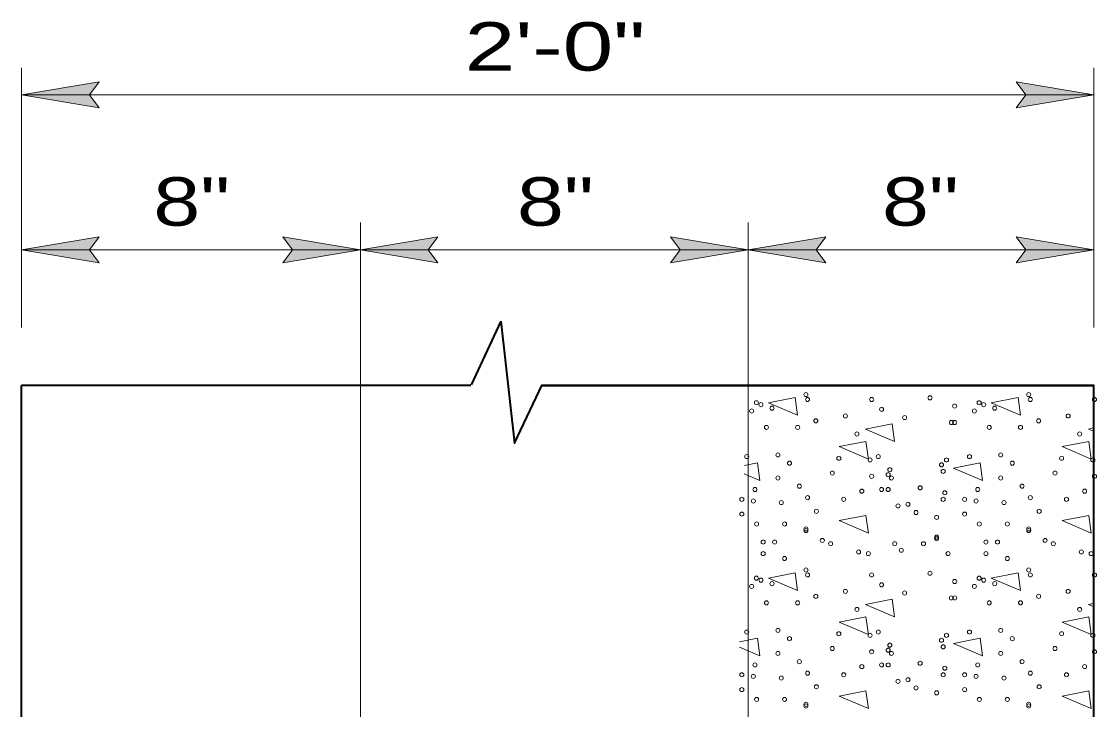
# Model space of a CAD drawing. Extents: x -43.06 to -36.2, y -1.41 to 7.25.
# Drawn here: x -41.507 to -40.176, y 3.704 to 4.557 of the extents above; entities that cross this region are included whole.
import ezdxf
from ezdxf.enums import TextEntityAlignment as Align

# ---------------------------------------------------------------- set-up
doc = ezdxf.new("R2010")
doc.units = 0
doc.header["$LTSCALE"] = 0.024
for name, color, linetype, lineweight in [('1', 7, 'Continuous', 35), ('10', 7, 'Continuous', 13), ('12', 7, 'Continuous', 53), ('6', 7, 'Continuous', 13)]:
    doc.layers.add(name, color=color, linetype=linetype, lineweight=lineweight)

msp = doc.modelspace()

# ---------------------------------------------------------------- hatches: boundary and pattern name
at = {"layer": '10'}
for points in [[(-41.50708, 4.46583), (-41.41108, 4.48183), (-41.42308, 4.46583), (-41.41108, 4.44983)], [(-40.17958, 4.46583), (-40.27558, 4.48183), (-40.26358, 4.46583), (-40.27558, 4.44983)], [(-41.50708, 4.27383), (-41.41108, 4.28983), (-41.42308, 4.27383), (-41.41108, 4.25783)], [(-41.08742, 4.27383), (-41.18342, 4.25783), (-41.17142, 4.27383), (-41.18342, 4.28983)], [(-41.08742, 4.27383), (-40.99142, 4.28983), (-41.00342, 4.27383), (-40.99142, 4.25783)], [(-40.60742, 4.27383), (-40.70342, 4.28983), (-40.69142, 4.27383), (-40.70342, 4.25783)], [(-40.60742, 4.27383), (-40.51142, 4.25783), (-40.52342, 4.27383), (-40.51142, 4.28983)], [(-40.17958, 4.27383), (-40.27558, 4.25783), (-40.26358, 4.27383), (-40.27558, 4.28983)]]:
    msp.add_hatch(color=256, dxfattribs=at).paths.add_polyline_path(points)

# ---------------------------------------------------------------- linework, layer by layer
at = {"layer": '1'}
for points in [[(-41.44342, 3.322), (-41.50708, 3.38567), (-41.50708, 4.10583)], [(-40.24325, 3.322), (-40.17958, 3.38567), (-40.17958, 4.10583)]]:
    msp.add_lwpolyline(points, dxfattribs=at)
at = {"layer": '10'}
for p, q in [((-41.50708, 4.17783), (-41.50708, 4.4995)), ((-40.17958, 4.17783), (-40.17958, 4.4995)), ((-41.41108, 4.48183), (-41.50708, 4.46583)), ((-41.41108, 4.48183), (-41.42308, 4.46583)), ((-40.27558, 4.48183), (-40.17958, 4.46583)), ((-40.27558, 4.48183), (-40.26358, 4.46583)), ((-41.50708, 4.46583), (-40.17958, 4.46583)), ((-41.41108, 4.44983), (-41.50708, 4.46583)), ((-41.41108, 4.44983), (-41.42308, 4.46583)), ((-40.27558, 4.44983), (-40.17958, 4.46583)), ((-40.27558, 4.44983), (-40.26358, 4.46583)), ((-41.08742, 3.574), (-41.08742, 4.30783)), ((-40.60742, 3.574), (-40.60742, 4.30783)), ((-41.41108, 4.28983), (-41.50708, 4.27383)), ((-41.41108, 4.28983), (-41.42308, 4.27383)), ((-41.18342, 4.28983), (-41.08742, 4.27383)), ((-41.18342, 4.28983), (-41.17142, 4.27383)), ((-40.99142, 4.28983), (-41.08742, 4.27383)), ((-40.99142, 4.28983), (-41.00342, 4.27383)), ((-40.70342, 4.28983), (-40.60742, 4.27383)), ((-40.70342, 4.28983), (-40.69142, 4.27383)), ((-40.51142, 4.28983), (-40.60742, 4.27383)), ((-40.51142, 4.28983), (-40.52342, 4.27383)), ((-40.27558, 4.28983), (-40.17958, 4.27383)), ((-40.27558, 4.28983), (-40.26358, 4.27383)), ((-41.41108, 4.25783), (-41.50708, 4.27383)), ((-41.41108, 4.25783), (-41.42308, 4.27383)), ((-41.18342, 4.25783), (-41.08742, 4.27383)), ((-41.18342, 4.25783), (-41.17142, 4.27383)), ((-40.99142, 4.25783), (-41.08742, 4.27383)), ((-40.99142, 4.25783), (-41.00342, 4.27383)), ((-40.70342, 4.25783), (-40.60742, 4.27383)), ((-40.70342, 4.25783), (-40.69142, 4.27383)), ((-40.51142, 4.25783), (-40.60742, 4.27383)), ((-40.51142, 4.25783), (-40.52342, 4.27383)), ((-40.27558, 4.25783), (-40.17958, 4.27383)), ((-40.27558, 4.25783), (-40.26358, 4.27383))]:
    msp.add_line(p, q, dxfattribs=at)
at = {"layer": '10', "lineweight": 35}
for p, q in [((-40.91358, 4.1855), (-40.95042, 4.1065)), ((-40.95092, 4.10583), (-41.50708, 4.10583)), ((-40.17958, 4.10583), (-40.86258, 4.10583))]:
    msp.add_line(p, q, dxfattribs=at)
at = {"layer": '10'}
for points in [[(-41.50708, 4.46583), (-41.41108, 4.48183), (-41.42308, 4.46583), (-41.41108, 4.44983)], [(-40.17958, 4.46583), (-40.27558, 4.48183), (-40.26358, 4.46583), (-40.27558, 4.44983)], [(-41.50708, 4.27383), (-41.41108, 4.28983), (-41.42308, 4.27383), (-41.41108, 4.25783)], [(-41.08742, 4.27383), (-41.18342, 4.25783), (-41.17142, 4.27383), (-41.18342, 4.28983)], [(-41.08742, 4.27383), (-40.99142, 4.28983), (-41.00342, 4.27383), (-40.99142, 4.25783)], [(-40.60742, 4.27383), (-40.70342, 4.28983), (-40.69142, 4.27383), (-40.70342, 4.25783)], [(-40.60742, 4.27383), (-40.51142, 4.25783), (-40.52342, 4.27383), (-40.51142, 4.28983)], [(-40.17958, 4.27383), (-40.27558, 4.25783), (-40.26358, 4.27383), (-40.27558, 4.28983)]]:
    msp.add_lwpolyline(points, close=True, dxfattribs=at)
msp.add_lwpolyline([(-41.50708, 4.27383), (-41.08742, 4.27383), (-40.60742, 4.27383), (-40.17958, 4.27383)], dxfattribs=at)
at = {"layer": '10', "lineweight": 35}
msp.add_lwpolyline([(-40.91358, 4.1855), (-40.89675, 4.0345), (-40.86258, 4.1065)], dxfattribs=at)
msp.add_lwpolyline([(-40.86292, 4.10583), (-40.86292, 4.10583), (-40.17958, 4.10583), (-40.17958, 4.10583)], close=True, dxfattribs=at)
at = {"layer": '6'}
for p, q in [((-40.18625, 4.05183), (-40.17975, 4.05317)), ((-40.17975, 4.04917), (-40.18625, 4.05183)), ((-40.18625, 3.8345), (-40.18025, 3.83567)), ((-40.18025, 3.832), (-40.18625, 3.8345))]:
    msp.add_line(p, q, dxfattribs=at)
for points in [[(-40.58225, 4.0845), (-40.54908, 4.091), (-40.54625, 4.06917)], [(-40.30642, 4.0845), (-40.27325, 4.091), (-40.27042, 4.06917)], [(-40.46208, 4.05183), (-40.42892, 4.05833), (-40.42608, 4.0365)], [(-40.49458, 4.03), (-40.46158, 4.0365), (-40.45858, 4.01467)], [(-40.21875, 4.03), (-40.18575, 4.0365), (-40.18275, 4.01467)], [(-40.35325, 4.0035), (-40.32008, 4.01), (-40.31725, 3.98817)], [(-40.49458, 3.93833), (-40.46158, 3.94483), (-40.45858, 3.923)], [(-40.21875, 3.93833), (-40.18575, 3.94483), (-40.18275, 3.923)], [(-40.58225, 3.86717), (-40.54908, 3.87367), (-40.54625, 3.85167)], [(-40.30642, 3.86717), (-40.27325, 3.87367), (-40.27042, 3.85167)], [(-40.46208, 3.8345), (-40.42892, 3.841), (-40.42608, 3.81917)], [(-40.49458, 3.81267), (-40.46158, 3.81917), (-40.45858, 3.79717)], [(-40.21875, 3.81267), (-40.18575, 3.81917), (-40.18275, 3.79717)], [(-40.35325, 3.78617), (-40.32008, 3.79267), (-40.31725, 3.77083)], [(-40.49458, 3.721), (-40.46158, 3.7275), (-40.45858, 3.70567)], [(-40.21875, 3.721), (-40.18575, 3.7275), (-40.18275, 3.70567)]]:
    msp.add_lwpolyline(points, close=True, dxfattribs=at)
for points in [[(-40.61192, 4.00683), (-40.59592, 4.01), (-40.59308, 3.98817), (-40.61225, 3.99633)], [(-40.61808, 3.78833), (-40.59592, 3.79267), (-40.59308, 3.77083), (-40.61825, 3.78167)]]:
    msp.add_lwpolyline(points, dxfattribs=at)
for centre in [(-40.59721, 4.08445), (-40.53588, 4.09453), (-40.53388, 4.08845), (-40.45447, 4.08845), (-40.38226, 4.09049), (-40.32141, 4.08445), (-40.26008, 4.09453), (-40.25808, 4.08845), (-40.17866, 4.08845), (-40.60309, 4.07421), (-40.59157, 4.08201), (-40.57793, 4.07765), (-40.44227, 4.07621), (-40.35173, 4.08029), (-40.32729, 4.07421), (-40.31576, 4.08201), (-40.30212, 4.07765), (-40.52368, 4.06197), (-40.48703, 4.06809), (-40.41374, 4.06605), (-40.35577, 4.05993), (-40.35173, 4.05993), (-40.24787, 4.06197), (-40.21123, 4.06809), (-40.58477, 4.05385), (-40.54608, 4.05385), (-40.47279, 4.04569), (-40.30896, 4.05385), (-40.27028, 4.05385), (-40.19699, 4.04569), (-40.60921, 4.01768), (-40.57053, 4.01972), (-40.44631, 4.01768), (-40.33341, 4.01768), (-40.29472, 4.01972), (-40.55624, 4.00952), (-40.49519, 4.01564), (-40.45651, 4.0136), (-40.36801, 4.00748), (-40.36189, 4.0136), (-40.28044, 4.00952), (-40.21939, 4.01564), (-40.1807, 4.0136), (-40.57053, 3.9912), (-40.50331, 3.99732), (-40.45447, 3.99324), (-40.4341, 3.99528), (-40.43206, 4.0014), (-40.43002, 3.9912), (-40.36597, 3.99936), (-40.29472, 3.9912), (-40.22751, 3.99732), (-40.17866, 3.99324), (-40.54404, 3.98104), (-40.39446, 3.979), (-40.26824, 3.98104), (-40.61529, 3.96475), (-40.59901, 3.97695), (-40.53388, 3.96679), (-40.48907, 3.96475), (-40.46667, 3.97491), (-40.44227, 3.97695), (-40.4341, 3.97695), (-40.36597, 3.96475), (-40.36393, 3.97287), (-40.33949, 3.96475), (-40.32321, 3.97695), (-40.25808, 3.96679), (-40.21327, 3.96475), (-40.19086, 3.97491), (-40.60105, 3.96271), (-40.56645, 3.96067), (-40.4219, 3.95659), (-40.40966, 3.95863), (-40.32525, 3.96271), (-40.29064, 3.96067), (-40.61529, 3.94643), (-40.52296, 3.94987), (-40.3995, 3.94847), (-40.37409, 3.94235), (-40.33949, 3.94643), (-40.24715, 3.94987), (-40.59697, 3.93419), (-40.56236, 3.93419), (-40.53588, 3.92811), (-40.53588, 3.92607), (-40.32117, 3.93419), (-40.28656, 3.93419), (-40.26008, 3.92811), (-40.26008, 3.92607), (-40.58885, 3.91182), (-40.57457, 3.91182), (-40.51556, 3.91382), (-40.37409, 3.91791), (-40.37409, 3.91587), (-40.31304, 3.91182), (-40.29876, 3.91182), (-40.23975, 3.91382), (-40.58885, 3.89754), (-40.50536, 3.90978), (-40.47075, 3.89958), (-40.45855, 3.89754), (-40.42594, 3.90978), (-40.41782, 3.90162), (-40.39038, 3.90978), (-40.35985, 3.89754), (-40.31304, 3.89754), (-40.22955, 3.90978), (-40.19495, 3.89958), (-40.18274, 3.89754), (-40.56236, 3.89146), (-40.28656, 3.89146), (-40.53588, 3.87718), (-40.53388, 3.8711), (-40.45447, 3.8711), (-40.38226, 3.87314), (-40.26008, 3.87718), (-40.25808, 3.8711), (-40.17866, 3.8711), (-40.59721, 3.8671), (-40.59157, 3.86466), (-40.57793, 3.8603), (-40.44227, 3.85886), (-40.35173, 3.86294), (-40.32141, 3.8671), (-40.31576, 3.86466), (-40.30212, 3.8603), (-40.60309, 3.85686), (-40.52368, 3.84461), (-40.48703, 3.85073), (-40.41374, 3.84869), (-40.32729, 3.85686), (-40.24787, 3.84461), (-40.21123, 3.85073), (-40.58477, 3.83649), (-40.54608, 3.83649), (-40.35577, 3.84257), (-40.35173, 3.84257), (-40.30896, 3.83649), (-40.27028, 3.83649), (-40.47279, 3.82833), (-40.19699, 3.82833), (-40.60921, 3.80033), (-40.57053, 3.80237), (-40.55624, 3.79217), (-40.49519, 3.79829), (-40.45651, 3.79625), (-40.44631, 3.80033), (-40.36189, 3.79625), (-40.33341, 3.80033), (-40.29472, 3.80237), (-40.28044, 3.79217), (-40.21939, 3.79829), (-40.1807, 3.79625), (-40.50331, 3.77996), (-40.4341, 3.77792), (-40.43206, 3.78404), (-40.36801, 3.79013), (-40.36597, 3.782), (-40.22751, 3.77996), (-40.57053, 3.77384), (-40.45447, 3.77588), (-40.43002, 3.77384), (-40.29472, 3.77384), (-40.17866, 3.77588), (-40.59901, 3.7596), (-40.54404, 3.76368), (-40.46667, 3.75756), (-40.44227, 3.7596), (-40.4341, 3.7596), (-40.39446, 3.76164), (-40.36393, 3.75552), (-40.32321, 3.7596), (-40.26824, 3.76368), (-40.19086, 3.75756), (-40.61529, 3.7474), (-40.60105, 3.74536), (-40.56645, 3.74332), (-40.53388, 3.74944), (-40.48907, 3.7474), (-40.4219, 3.73924), (-40.40966, 3.74128), (-40.36597, 3.7474), (-40.33949, 3.7474), (-40.32525, 3.74536), (-40.29064, 3.74332), (-40.25808, 3.74944), (-40.21327, 3.7474), (-40.61529, 3.72908), (-40.52296, 3.73252), (-40.3995, 3.73112), (-40.37409, 3.72499), (-40.33949, 3.72908), (-40.24715, 3.73252), (-40.59697, 3.71683), (-40.56236, 3.71683), (-40.32117, 3.71683), (-40.28656, 3.71683), (-40.53588, 3.71075), (-40.53588, 3.70871), (-40.26008, 3.71075), (-40.26008, 3.70871)]:
    msp.add_circle(centre, 0.00252, dxfattribs=at)

# ---------------------------------------------------------------- texts
at = {"layer": '12'}
for s, width, p in [('2\'-0"', 1.4, (-40.84654, 4.49583)), ('8"', 1.3, (-41.29633, 4.30375)), ('8"', 1.3, (-40.84608, 4.30375)), ('8"', 1.3, (-40.39417, 4.30375))]:
    msp.add_text(s, height=0.06001, dxfattribs=dict(at, width=width)).set_placement(p, align=Align.CENTER)

doc.saveas('drawing.dxf')
